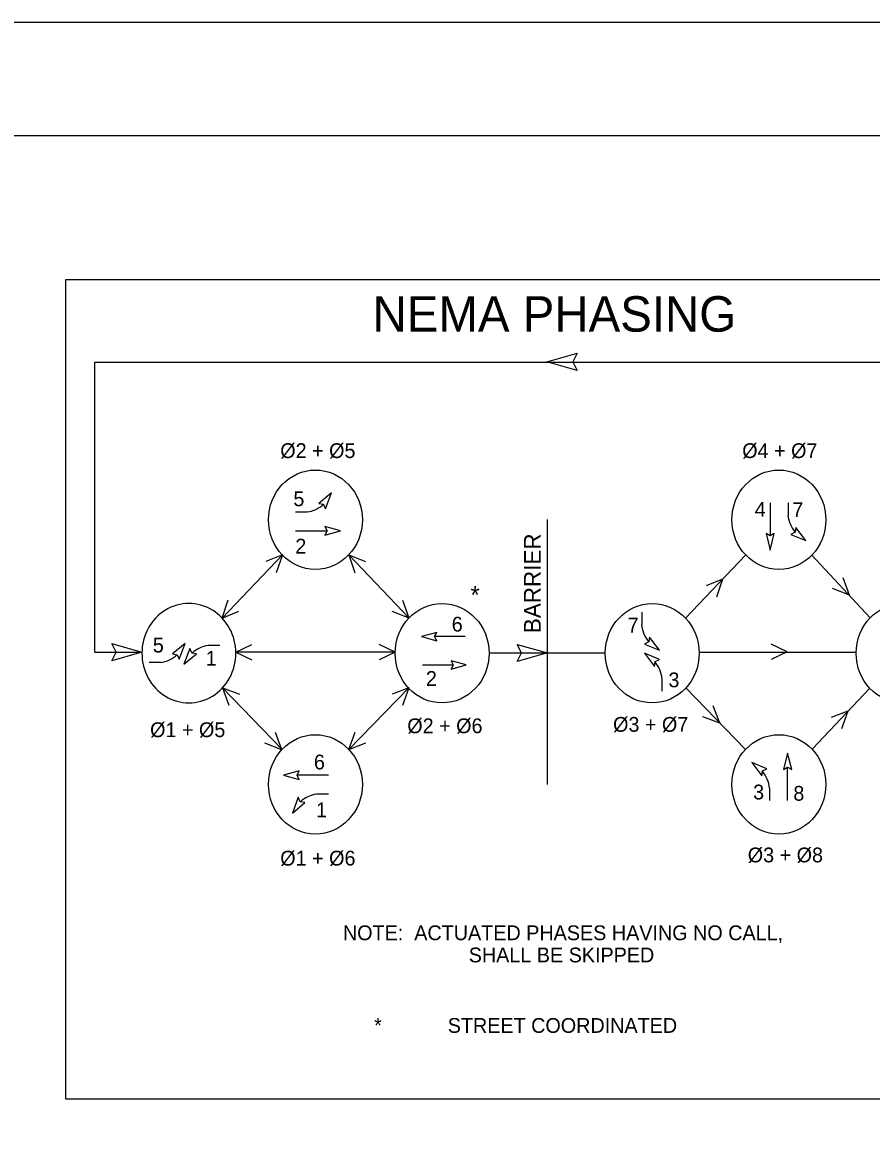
# Model space of a CAD drawing. Extents: x 0 to 3.01, y -0.05 to 1.83.
# Drawn here: x 0.734 to 1.168, y 1.255 to 1.833 of the extents above; entities that cross this region are included whole.
import ezdxf

# ---------------------------------------------------------------- set-up
doc = ezdxf.new("R2010")
doc.units = 0
for name, color, linetype in [('RD_SHT_IplotShp', 7, 'Continuous'), ('TR_TS_Border', 7, 'Continuous'), ('TR_TS_Phase1', 7, 'Continuous'), ('TR_TS_Phase2', 7, 'Continuous'), ('TR_TS_Phase3', 7, 'Continuous'), ('TR_TS_Phase5', 7, 'Continuous'), ('TR_TS_Phase6', 7, 'Continuous'), ('TR_TS_Phase7', 7, 'Continuous')]:
    doc.layers.add(name, color=color, linetype=linetype)

msp = doc.modelspace()

# ---------------------------------------------------------------- linework, layer by layer
at = {"layer": 'RD_SHT_IplotShp'}
msp.add_lwpolyline([(0, 0), (3, 0), (3, 1.83333), (0, 1.83333)], close=True, dxfattribs=at)
at = {"layer": 'TR_TS_Border'}
for p, q in [((2.94187, 1.83333), (0.031, 1.83333)), ((2.96235, 1.7754), (0.16861, 1.7754)), ((1.00185, 1.65988), (1.01734, 1.66431)), ((1.01734, 1.66431), (1.01512, 1.65988)), ((0.7706, 1.6596), (1.24441, 1.6596)), ((0.7706, 1.51138), (0.7706, 1.6596)), ((1.01734, 1.65546), (1.00185, 1.65988)), ((1.01512, 1.65988), (1.01734, 1.65546)), ((1.00203, 1.44362), (1.00203, 1.57914)), ((0.83567, 1.52879), (0.86647, 1.56116)), ((0.86647, 1.56116), (0.85801, 1.55768)), ((0.86647, 1.56116), (0.86335, 1.55184)), ((0.90047, 1.56116), (0.93127, 1.52879)), ((0.90047, 1.56116), (0.90893, 1.55768)), ((0.90047, 1.56116), (0.90358, 1.55184)), ((1.07271, 1.52879), (1.10351, 1.56116)), ((1.13742, 1.56097), (1.16715, 1.52897)), ((1.09167, 1.54874), (1.08321, 1.54526)), ((1.09167, 1.54874), (1.08855, 1.53951)), ((1.15656, 1.54046), (1.15335, 1.5494)), ((1.15656, 1.54046), (1.14792, 1.54384)), ((0.83567, 1.52879), (0.83878, 1.5381)), ((0.93127, 1.52879), (0.92806, 1.53773)), ((0.83567, 1.52879), (0.84412, 1.53227)), ((0.93127, 1.52879), (0.92272, 1.53217)), ((0.78137, 1.51138), (0.77915, 1.5158)), ((0.77915, 1.5158), (0.79463, 1.51138)), ((0.84261, 1.51138), (0.85089, 1.51533)), ((0.92424, 1.51138), (0.91596, 1.51533)), ((0.98877, 1.51091), (0.98654, 1.51533)), ((0.98654, 1.51533), (1.00203, 1.51091)), ((1.12469, 1.51147), (1.1165, 1.51542)), ((0.7706, 1.51138), (0.79463, 1.51138)), ((0.77915, 1.50695), (0.78137, 1.51138)), ((0.79463, 1.51138), (0.77915, 1.50695)), ((0.92424, 1.51138), (0.84261, 1.51138)), ((0.84261, 1.51138), (0.85089, 1.50742)), ((0.92424, 1.51138), (0.91596, 1.50742)), ((0.9723, 1.51091), (1.03167, 1.51091)), ((0.98654, 1.50648), (0.98877, 1.51091)), ((1.00203, 1.51091), (0.98654, 1.50648)), ((1.07974, 1.51138), (1.16003, 1.51138)), ((1.12469, 1.51147), (1.1165, 1.50752)), ((0.86629, 1.46159), (0.83585, 1.49312)), ((0.83585, 1.49312), (0.83905, 1.48427)), ((0.83585, 1.49312), (0.84448, 1.48982)), ((0.93109, 1.49312), (0.90056, 1.46159)), ((0.93109, 1.49312), (0.92263, 1.48982)), ((0.93109, 1.49312), (0.92788, 1.48408)), ((1.10342, 1.46159), (1.07289, 1.49312)), ((1.16706, 1.49293), (1.13751, 1.46178)), ((1.09024, 1.47505), (1.08695, 1.48389)), ((1.15576, 1.48117), (1.14721, 1.47787)), ((1.15576, 1.48117), (1.15255, 1.47213)), ((1.09024, 1.47505), (1.08161, 1.47834)), ((0.86615, 1.46143), (0.86294, 1.47027)), ((0.90056, 1.46159), (0.90376, 1.47044)), ((0.86615, 1.46143), (0.85751, 1.46472)), ((0.90056, 1.46159), (0.90919, 1.46488))]:
    msp.add_line(p, q, dxfattribs=at)
msp.add_lwpolyline([(0.75574, 1.70195), (1.26043, 1.70195), (1.26043, 1.28268), (0.75574, 1.28268)], close=True, dxfattribs=at)
for centre in [(0.88338, 1.57906), (1.1205, 1.57906), (0.94819, 1.51079), (1.0557, 1.51079), (1.18403, 1.51079), (0.88338, 1.44371), (1.1205, 1.44371)]:
    msp.add_ellipse(centre, major_axis=(0, 0.02541), ratio=0.945811, dxfattribs=at)
for start_param, end_param in [(4.712389, 7.853982), (1.570796, 4.712389)]:
    msp.add_ellipse((0.81865, 1.51079), major_axis=(0, 0.02541), ratio=0.945811, start_param=start_param, end_param=end_param, dxfattribs=at)
at = {"layer": 'TR_TS_Phase1'}
for p, q in [((0.83454, 1.5148), (0.8285, 1.5148)), ((0.88999, 1.44841), (0.87396, 1.44841)), ((0.88999, 1.43873), (0.88394, 1.43873))]:
    msp.add_line(p, q, dxfattribs=at)
for points in [[(0.8203, 1.5109), (0.82016, 1.51093), (0.81916, 1.51325), (0.81613, 1.50512), (0.82255, 1.51054), (0.8203, 1.5109)], [(0.87506, 1.45064), (0.86709, 1.44841), (0.87506, 1.44619), (0.87396, 1.44841), (0.87506, 1.45064)], [(0.87575, 1.43484), (0.87561, 1.43486), (0.8746, 1.43718), (0.87158, 1.42905), (0.87799, 1.43447), (0.87575, 1.43484)]]:
    msp.add_lwpolyline(points, dxfattribs=at)
for centre, end_param in [((0.83056, 1.49805), 0.700777), ((0.88602, 1.42199), 0.701762)]:
    msp.add_ellipse(centre, major_axis=(0, 0.01682), ratio=0.945811, start_param=0.132601, end_param=end_param, dxfattribs=at)
at = {"layer": 'TR_TS_Phase2'}
msp.add_line((0.93821, 1.50479), (0.95388, 1.50479), dxfattribs=at)
msp.add_lwpolyline([(0.95281, 1.50262), (0.96055, 1.50479), (0.95281, 1.50695), (0.95388, 1.50479), (0.95281, 1.50262)], dxfattribs=at)
at = {"layer": 'TR_TS_Phase3'}
for p, q in [((1.06086, 1.49136), (1.06086, 1.49775)), ((1.12493, 1.43549), (1.12493, 1.45244)), ((1.11578, 1.43549), (1.11578, 1.44179))]:
    msp.add_line(p, q, dxfattribs=at)
for points in [[(1.05716, 1.50631), (1.0572, 1.50657), (1.05939, 1.50763), (1.0517, 1.51083), (1.05683, 1.50405), (1.05716, 1.50631)], [(1.12704, 1.45128), (1.12493, 1.4597), (1.12283, 1.45128), (1.12493, 1.45244), (1.12704, 1.45128)], [(1.11209, 1.45044), (1.11211, 1.4506), (1.11431, 1.45166), (1.10662, 1.45486), (1.11175, 1.44808), (1.11209, 1.45044)]]:
    msp.add_lwpolyline(points, dxfattribs=at)
for centre, end_param in [((1.04501, 1.49545), 5.427381), ((1.09998, 1.43953), 5.417976)]:
    msp.add_ellipse(centre, major_axis=(0, 0.01682), ratio=0.945811, start_param=4.84499, end_param=end_param, dxfattribs=at)
at = {"layer": 'TR_TS_Phase5'}
for p, q in [((0.87319, 1.58307), (0.87923, 1.58307)), ((0.87319, 1.57339), (0.88931, 1.57339)), ((0.79827, 1.50616), (0.80432, 1.50616))]:
    msp.add_line(p, q, dxfattribs=at)
for points in [[(0.88746, 1.58696), (0.88757, 1.58694), (0.88858, 1.58462), (0.8916, 1.59275), (0.88519, 1.58733), (0.88746, 1.58696)], [(0.88821, 1.57116), (0.89618, 1.57339), (0.88821, 1.57561), (0.88931, 1.57339), (0.88821, 1.57116)], [(0.81258, 1.51004), (0.81265, 1.51003), (0.81366, 1.50771), (0.81668, 1.51584), (0.81027, 1.51042), (0.81258, 1.51004)]]:
    msp.add_lwpolyline(points, dxfattribs=at)
for centre, end_param in [((0.87708, 1.5997), 0.715547), ((0.80214, 1.52273), 0.719657)]:
    msp.add_ellipse(centre, major_axis=(0, -0.01682), ratio=0.945811, start_param=0.132601, end_param=end_param, dxfattribs=at)
at = {"layer": 'TR_TS_Phase6'}
msp.add_line((0.95993, 1.51928), (0.94435, 1.51928), dxfattribs=at)
msp.add_lwpolyline([(0.94542, 1.52145), (0.93768, 1.51928), (0.94542, 1.51712), (0.94435, 1.51928), (0.94542, 1.52145)], dxfattribs=at)
at = {"layer": 'TR_TS_Phase7'}
for p, q in [((1.11602, 1.58774), (1.11602, 1.5708)), ((1.12518, 1.58774), (1.12518, 1.58145)), ((1.05033, 1.53174), (1.05033, 1.52535))]:
    msp.add_line(p, q, dxfattribs=at)
for points in [[(1.11392, 1.57196), (1.11602, 1.56354), (1.11813, 1.57196), (1.11602, 1.5708), (1.11392, 1.57196)], [(1.12882, 1.57263), (1.12665, 1.57158), (1.13434, 1.56838), (1.12921, 1.57516), (1.12884, 1.57264), (1.12882, 1.57263)], [(1.05391, 1.51659), (1.0539, 1.51654), (1.0517, 1.51547), (1.05939, 1.51228), (1.05427, 1.51906), (1.05391, 1.51659)]]:
    msp.add_lwpolyline(points, dxfattribs=at)
for centre, end_param in [((1.1409, 1.58358), 5.421194), ((1.066, 1.52752), 5.422668)]:
    msp.add_ellipse(centre, major_axis=(0, -0.01682), ratio=0.945811, start_param=4.84499, end_param=end_param, dxfattribs=at)

# ---------------------------------------------------------------- texts
at = {"layer": 'TR_TS_Border'}
for s, height, p in [('NEMA PHASING', 0.0181389, (0.91262, 1.67525)), ('Ø2 + Ø5', 0.007558, (0.86539, 1.61061)), ('Ø4 + Ø7', 0.007558, (1.10174, 1.61061)), ('*', 0.00907, (0.96272, 1.53612)), ('Ø1 + Ø5', 0.007558, (0.79881, 1.46788)), ('Ø2 + Ø6', 0.007558, (0.93039, 1.46989)), ('Ø3 + Ø7', 0.007558, (1.03567, 1.47062)), ('Ø1 + Ø6', 0.007558, (0.86539, 1.4022)), ('Ø3 + Ø8', 0.007558, (1.10457, 1.40384)), ('NOTE:  ACTUATED PHASES HAVING NO CALL,', 0.0075579, (0.89745, 1.36403)), ('SHALL BE SKIPPED', 0.0075579, (0.96182, 1.35269)), ('*            STREET COORDINATED', 0.0075579, (0.91345, 1.31663))]:
    msp.add_text(s, height=height, dxfattribs=at).set_placement(p)
msp.add_text('BARRIER', height=0.008578, rotation=90, dxfattribs=at).set_placement((0.99867, 1.52107))
at = {"layer": 'TR_TS_Phase1'}
for s, p in [('1', (0.82728, 1.50443)), ('6', (0.88261, 1.45137)), ('1', (0.88373, 1.42692))]:
    msp.add_text(s, height=0.00756, dxfattribs=at).set_placement(p)
at = {"layer": 'TR_TS_Phase2'}
msp.add_text('2', height=0.00756, dxfattribs=at).set_placement((0.93989, 1.49409))
at = {"layer": 'TR_TS_Phase3'}
for s, p in [('3', (1.06399, 1.49338)), ('3', (1.10731, 1.43602)), ('8', (1.12788, 1.43536))]:
    msp.add_text(s, height=0.00756, dxfattribs=at).set_placement(p)
at = {"layer": 'TR_TS_Phase5'}
for s, p in [('5', (0.87212, 1.58598)), ('2', (0.87309, 1.56179)), ('5', (0.80021, 1.51117))]:
    msp.add_text(s, height=0.00756, dxfattribs=at).set_placement(p)
at = {"layer": 'TR_TS_Phase6'}
msp.add_text('6', height=0.00756, dxfattribs=at).set_placement((0.95312, 1.52186))
at = {"layer": 'TR_TS_Phase7'}
for s, p in [('4', (1.10811, 1.58056)), ('7', (1.12735, 1.58041)), ('7', (1.0431, 1.52138))]:
    msp.add_text(s, height=0.00756, dxfattribs=at).set_placement(p)

doc.saveas('drawing.dxf')
